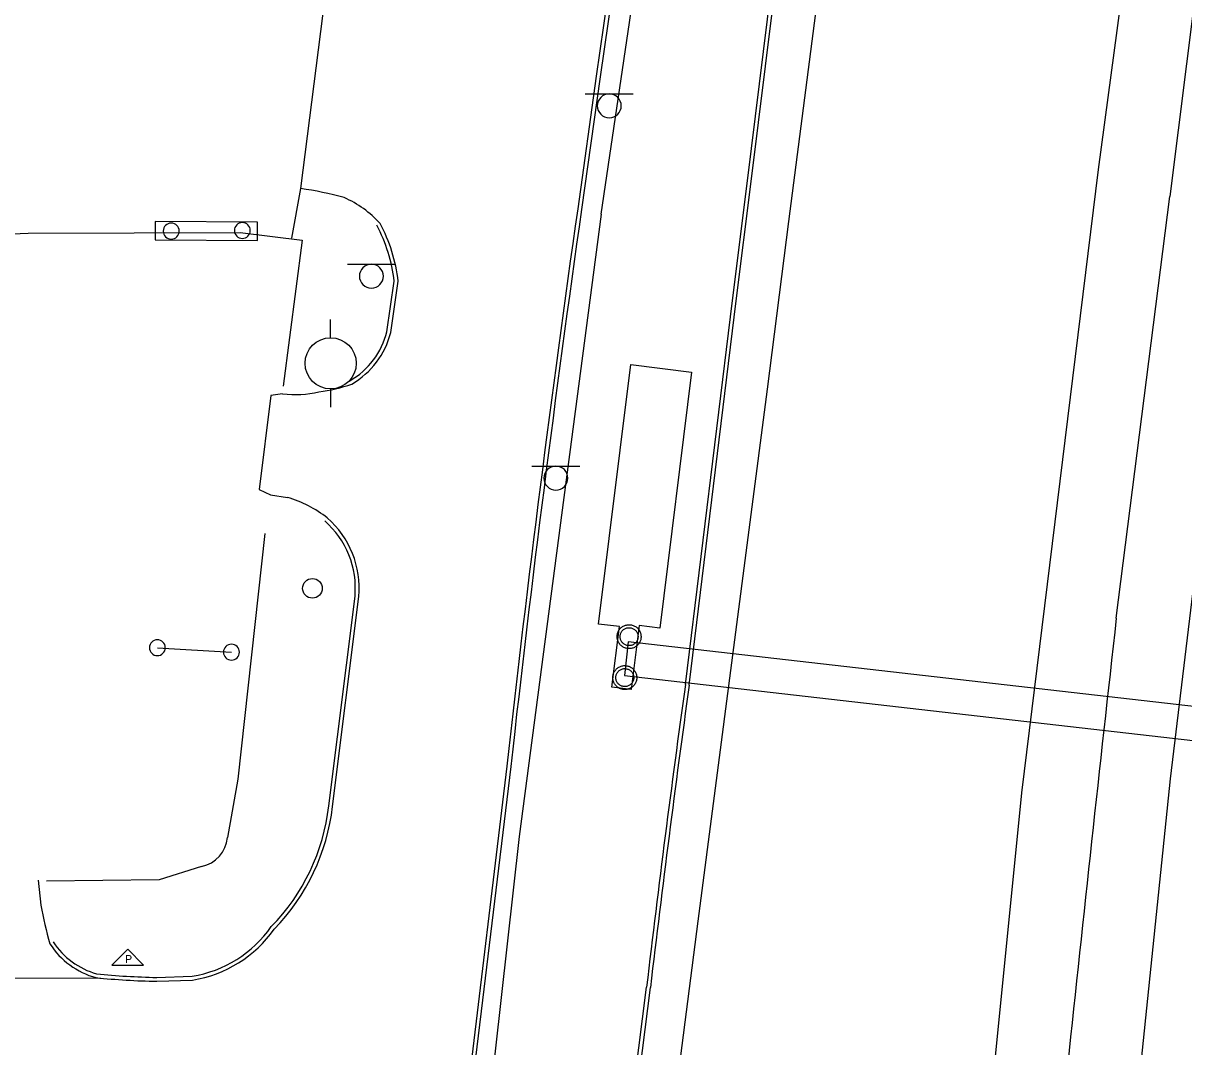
# Model space of a CAD drawing. Extents: x 2145380 to 2156929, y 139568 to 149130.
# Drawn here: x 2150672.3 to 2150853.5, y 146965.7 to 147125.6 of the extents above; entities that cross this region are included whole.
import ezdxf

# ---------------------------------------------------------------- set-up
doc = ezdxf.new("R2010")
doc.units = 0
for name, color, linetype in [('Default', 7, 'Continuous'), ('TOPO_Asphalt', 7, 'Continuous'), ('TOPO_Concrete', 7, 'Continuous'), ('TOPO_Curb Back', 7, 'Continuous'), ('TOPO_Fence', 7, 'Continuous'), ('TOPO_Guardrail', 7, 'Continuous'), ('TOPO_Misc', 7, 'Continuous'), ('TOPO_Power Pole', 7, 'Continuous'), ('TOPO_Sign', 7, 'Continuous'), ('TOPO_Wall Freestanding', 7, 'Continuous'), ('TOPO_Water Meter', 7, 'Continuous')]:
    doc.layers.add(name, color=color, linetype=linetype)

# ---------------------------------------------------------------- blocks, each defined once
blk = doc.blocks.new('POST')
at = {"layer": 'TOPO_Misc'}
for start, end in [(90, 180), (180, 270), (360, 90), (270, 0)]:
    blk.add_arc((-0.01, 0.03), 3.16, start, end, dxfattribs=at)
blk = doc.blocks.new('POWPOL')
at = {"layer": 'TOPO_Power Pole'}
for p, q in [((0, 10.16), (0, 17.34)), ((0, -10.16), (0, -17.34))]:
    blk.add_line(p, q, dxfattribs=at)
blk.add_circle((0, 0), 10.16, dxfattribs=at)
blk = doc.blocks.new('WTRMTR')
at = {"layer": 'Default'}
blk.add_circle((0, 0), 3.89, dxfattribs=at)

msp = doc.modelspace()

# ---------------------------------------------------------------- linework, layer by layer
at = {"layer": 'TOPO_Asphalt'}
for p, q in [((2150720.04, 147134.92), (2150715.57, 147099.73)), ((2150684.32, 146976.41), (2150650.56, 146976.32))]:
    msp.add_line(p, q, dxfattribs=at)
for points in [[(2151148.58, 148387.71), (2151085.35, 148183.97), (2151069.92, 148133.07), (2151057.83, 148094.37), (2151049.57, 148067.66), (2151035.93, 148022.98), (2151024.64, 147984.83), (2151012.64, 147943.42), (2151001.98, 147906), (2150990.9, 147865.2), (2150980.73, 147826.5), (2150968.97, 147781.23), (2150957.45, 147734.97), (2150948.5, 147698.21), (2150935.23, 147640.33), (2150928.26, 147609.37), (2150921.99, 147580.12), (2150903.41, 147490.92), (2150881.14, 147370.04), (2150865.32, 147276.63), (2150852.01, 147191.15), (2150840.13, 147102.7), (2150828.19, 147005.35), (2150817.7, 146900.58)], [(2150767.42, 146905.57), (2150777.66, 146985.28), (2150788.49, 147068.42), (2150791.81, 147094.61), (2150804.99, 147196.42), (2150817.4, 147289.05), (2150831.55, 147394.21), (2150843.61, 147487.04), (2150852.06, 147556.43)], [(2150819.78, 146571.32), (2150823.49, 146659.32), (2150828.97, 146758.61), (2150835.17, 146838.37), (2150842.86, 146924.28), (2150851.46, 147007.54), (2150862.87, 147102.56)], [(2150715.57, 147099.73), (2150714.18, 147092.01)], [(2150712.76, 147067.68), (2150710.93, 147067.41), (2150709.09, 147052.73), (2150710.88, 147051.89)], [(2150710.88, 147051.89), (2150713.55, 147051.5)], [(2150705.79, 147007.51), (2150704.16, 146998.38)], [(2150700.11, 146993.86), (2150693.5, 146991.77)], [(2150674.58, 146991.7), (2150675.01, 146987.81)]]:
    msp.add_lwpolyline(points, dxfattribs=at)
for centre, radius, start, end in [((2150708.73, 147049.63), 50.56, 74.3331, 82.2233), ((2150715.59, 147082.93), 16.82, 42.5079, 66.1666), ((2150715.52, 147091.91), 24.09, 276.9505, 289.5316), ((2150714.72, 147083.62), 16.06, 262.9859, 283.3625), ((2150707.95, 147033.11), 19.22, 52.1382, 73.0648), ((2150699.09, 146998.85), 5.1, 281.5826, 354.6962), ((2150736.07, 146998.83), 62.04, 190.2315, 195.9833)]:
    msp.add_arc(centre, radius, start, end, dxfattribs=at)
at = {"layer": 'TOPO_Concrete'}
msp.add_lwpolyline([(2150776.62, 147071.07), (2150771.68, 147031.09), (2150768.44, 147031.49), (2150767.21, 147021.51), (2150764.2, 147021.88), (2150765.37, 147031.32), (2150762.11, 147031.72), (2150767.13, 147072.25), (2150776.62, 147071.07)], dxfattribs=at)
at = {"layer": 'TOPO_Curb Back'}
for points in [[(2150846.01, 147581.74), (2150829.56, 147505.33), (2150818.69, 147452.43), (2150805.18, 147383.38), (2150793.7, 147320.64), (2150782.04, 147252.39), (2150770.34, 147176.72), (2150761.75, 147117.28), (2150758.85, 147096.56)], [(2150846.6, 147581.61), (2150830.15, 147505.21), (2150819.28, 147452.31), (2150805.77, 147383.26), (2150794.29, 147320.54), (2150782.63, 147252.3), (2150770.93, 147176.63), (2150762.35, 147117.2), (2150759.45, 147096.48)], [(2150775.68, 147022.26), (2150783.01, 147082.27), (2150785.37, 147100.94), (2150796.59, 147191.47), (2150808.98, 147283.55), (2150821.25, 147374.74), (2150832.7, 147461.73), (2150841, 147522.44), (2150851.09, 147556.17), (2150852.78, 147567.37)], [(2150776.27, 147022.18), (2150783.6, 147082.2), (2150785.97, 147100.86), (2150797.19, 147191.39), (2150809.57, 147283.47), (2150821.85, 147374.66), (2150833.3, 147461.65), (2150841.59, 147522.31), (2150851.68, 147556.04), (2150853.38, 147567.28)], [(2150729.07, 147077.38), (2150730.21, 147085.26)], [(2150729.66, 147077.26), (2150730.81, 147085.25)], [(2150719.97, 147003.3), (2150724.08, 147036.07)], [(2150720.57, 147003.23), (2150724.68, 147036)], [(2150747.79, 147009.54), (2150741.49, 146957.15), (2150734.18, 146889.26), (2150729.72, 146841.78), (2150726.33, 146801.59), (2150720.25, 146730.98), (2150714.67, 146662.78), (2150709.31, 146595.34), (2150703.43, 146516.5), (2150699.73, 146456.09), (2150696.04, 146382.8), (2150693.17, 146306.56), (2150691.24, 146222.87)], [(2150748.39, 147009.47), (2150742.08, 146957.08), (2150734.78, 146889.2), (2150730.32, 146841.72), (2150726.93, 146801.54), (2150720.84, 146730.93), (2150715.27, 146662.73), (2150709.91, 146595.3), (2150704.03, 146516.46), (2150700.33, 146456.06), (2150696.64, 146382.77), (2150693.77, 146306.54), (2150691.84, 146222.89)], [(2150693.09, 146976.52), (2150698.64, 146976.71)], [(2150693.1, 146975.92), (2150698.69, 146976.11)], [(2150716.37, 146556.85), (2150721.79, 146599.22), (2150730.66, 146669.12), (2150740.14, 146743.09), (2150749.46, 146815.03), (2150759.33, 146893.84), (2150769.62, 146975.01)], [(2150716.96, 146556.77), (2150722.39, 146599.15), (2150731.25, 146669.04), (2150740.73, 146743.01), (2150750.05, 146814.95), (2150759.92, 146893.77), (2150770.21, 146974.93)]]:
    msp.add_lwpolyline(points, dxfattribs=at)
for centre, radius, start, end in [((2153641.09, 146686.03), 2911.33, 171.89362, 173.62008), ((2153641.1, 146686.03), 2910.73, 171.89362, 173.62013), ((2150705.63, 147082.36), 24.75, 6.7241, 28.0992), ((2150705.63, 147082.36), 25.35, 6.5451, 28.099), ((2150717.13, 147080.39), 12.31, 299.9281, 345.8191), ((2150717.13, 147080.39), 12.91, 299.9276, 345.9591), ((2150710.21, 147037.32), 13.92, 354.8256, 48.9968), ((2150710.21, 147037.32), 14.52, 354.7849, 48.9964), ((2153014.01, 146711.08), 2259.86, 172.08526, 173.29311), ((2153014.94, 146710.95), 2260.2, 172.08526, 173.2928), ((2150687.84, 147007.04), 32.35, 315.713, 353.3641), ((2150687.84, 147007.04), 32.95, 315.798, 353.3595), ((2150695.71, 146995.13), 18.65, 279.0322, 325.063), ((2150695.71, 146995.13), 19.25, 278.9215, 324.9164), ((2150687.07, 146988.73), 12.73, 213.2757, 254.2011), ((2150687.07, 146988.73), 12.13, 213.2769, 253.9546), ((2150695.16, 147090.94), 115.04, 264.2353, 268.976), ((2150695.16, 147090.96), 114.46, 264.2626, 268.9679)]:
    msp.add_arc(centre, radius, start, end, dxfattribs=at)
at = {"layer": 'TOPO_Fence'}
for points in [[(2150762.5, 147095.73), (2150785.02, 147247.97), (2150805.17, 147364.3), (2150828.19, 147482.1)], [(2150762.52, 147095.73), (2150749.72, 146998.54), (2150739.48, 146906.78), (2150733.13, 146841.34), (2150726.96, 146767.54), (2150718.56, 146664.61), (2150710.62, 146567.84)]]:
    msp.add_lwpolyline(points, dxfattribs=at)
at = {"layer": 'TOPO_Guardrail'}
for p, q in [((2150710.01, 147045.86), (2150705.78, 147007.49)), ((2150693.5, 146991.77), (2150675.9, 146991.57))]:
    msp.add_line(p, q, dxfattribs=at)
msp.add_lwpolyline([(2150630.33, 147091.01), (2150673.02, 147092.77), (2150706.14, 147092.86), (2150715.82, 147091.66), (2150712.88, 147068.88)], dxfattribs=at)
at = {"layer": 'TOPO_Misc'}
for p, q in [((2150688.57, 146980.95), (2150686.07, 146978.45)), ((2150691.06, 146978.45), (2150688.57, 146980.95)), ((2150686.07, 146978.45), (2150691.06, 146978.45))]:
    msp.add_line(p, q, dxfattribs=at)
at = {"layer": 'TOPO_Power Pole'}
for points in [[(2150765.01, 147029.74), (2150765.01, 147029.87), (2150765.03, 147030), (2150765.05, 147030.13), (2150765.09, 147030.26), (2150765.13, 147030.38), (2150765.18, 147030.51), (2150765.24, 147030.63), (2150765.3, 147030.74), (2150765.38, 147030.85), (2150765.46, 147030.96), (2150765.55, 147031.05), (2150765.64, 147031.15), (2150765.75, 147031.23), (2150765.86, 147031.31), (2150765.97, 147031.37), (2150766.09, 147031.43), (2150766.21, 147031.48), (2150766.33, 147031.53), (2150766.46, 147031.56), (2150766.6, 147031.59), (2150766.73, 147031.61), (2150766.86, 147031.61), (2150766.99, 147031.61), (2150767.12, 147031.59), (2150767.25, 147031.58), (2150767.37, 147031.54), (2150767.5, 147031.51), (2150767.62, 147031.45), (2150767.75, 147031.4), (2150767.86, 147031.34), (2150767.97, 147031.26), (2150768.08, 147031.18), (2150768.17, 147031.1), (2150768.27, 147031), (2150768.35, 147030.9), (2150768.43, 147030.79), (2150768.5, 147030.68), (2150768.57, 147030.56), (2150768.62, 147030.44), (2150768.66, 147030.31), (2150768.7, 147030.19), (2150768.73, 147030.06), (2150768.74, 147029.92), (2150768.75, 147029.79), (2150768.75, 147029.67), (2150768.74, 147029.53), (2150768.72, 147029.4), (2150768.69, 147029.27), (2150768.65, 147029.15), (2150768.61, 147029.02), (2150768.55, 147028.91), (2150768.49, 147028.79), (2150768.42, 147028.68), (2150768.34, 147028.57), (2150768.25, 147028.46), (2150768.16, 147028.37), (2150768.06, 147028.29), (2150767.95, 147028.21), (2150767.84, 147028.14), (2150767.73, 147028.07), (2150767.61, 147028.02), (2150767.48, 147027.97), (2150767.35, 147027.93), (2150767.23, 147027.9), (2150767.09, 147027.88), (2150766.96, 147027.87), (2150766.84, 147027.87), (2150766.71, 147027.88), (2150766.58, 147027.89), (2150766.44, 147027.92), (2150766.32, 147027.96), (2150766.19, 147028.01), (2150766.07, 147028.06), (2150765.95, 147028.12), (2150765.84, 147028.19), (2150765.73, 147028.27), (2150765.63, 147028.35), (2150765.54, 147028.44), (2150765.45, 147028.54), (2150765.37, 147028.65), (2150765.29, 147028.76), (2150765.23, 147028.87), (2150765.17, 147028.99), (2150765.12, 147029.12), (2150765.08, 147029.24), (2150765.05, 147029.36), (2150765.03, 147029.5), (2150765.01, 147029.63), (2150765.01, 147029.74)], [(2150765.48, 147029.74), (2150765.48, 147029.85), (2150765.5, 147029.97), (2150765.52, 147030.08), (2150765.56, 147030.19), (2150765.59, 147030.3), (2150765.64, 147030.4), (2150765.7, 147030.49), (2150765.77, 147030.59), (2150765.84, 147030.68), (2150765.92, 147030.76), (2150766.01, 147030.84), (2150766.11, 147030.91), (2150766.2, 147030.96), (2150766.3, 147031.01), (2150766.41, 147031.06), (2150766.52, 147031.1), (2150766.63, 147031.12), (2150766.74, 147031.14), (2150766.86, 147031.14), (2150766.97, 147031.14), (2150767.08, 147031.13), (2150767.2, 147031.11), (2150767.31, 147031.07), (2150767.41, 147031.04), (2150767.52, 147030.99), (2150767.61, 147030.93), (2150767.71, 147030.87), (2150767.8, 147030.8), (2150767.89, 147030.72), (2150767.96, 147030.63), (2150768.03, 147030.54), (2150768.09, 147030.44), (2150768.15, 147030.34), (2150768.19, 147030.24), (2150768.23, 147030.13), (2150768.26, 147030.02), (2150768.27, 147029.9), (2150768.28, 147029.79), (2150768.28, 147029.68), (2150768.27, 147029.57), (2150768.25, 147029.46), (2150768.23, 147029.34), (2150768.19, 147029.23), (2150768.14, 147029.13), (2150768.09, 147029.03), (2150768.03, 147028.93), (2150767.96, 147028.84), (2150767.88, 147028.76), (2150767.8, 147028.68), (2150767.7, 147028.61), (2150767.61, 147028.55), (2150767.51, 147028.49), (2150767.4, 147028.44), (2150767.3, 147028.4), (2150767.18, 147028.37), (2150767.07, 147028.35), (2150766.95, 147028.34), (2150766.85, 147028.34), (2150766.74, 147028.35), (2150766.63, 147028.36), (2150766.51, 147028.38), (2150766.4, 147028.42), (2150766.3, 147028.46), (2150766.19, 147028.52), (2150766.1, 147028.58), (2150766, 147028.65), (2150765.92, 147028.72), (2150765.84, 147028.81), (2150765.76, 147028.9), (2150765.69, 147028.99), (2150765.64, 147029.09), (2150765.59, 147029.19), (2150765.55, 147029.3), (2150765.52, 147029.41), (2150765.5, 147029.52), (2150765.48, 147029.64), (2150765.48, 147029.74)], [(2150764.33, 147023.35), (2150764.34, 147023.48), (2150764.35, 147023.61), (2150764.38, 147023.73), (2150764.41, 147023.87), (2150764.45, 147023.99), (2150764.5, 147024.12), (2150764.56, 147024.23), (2150764.63, 147024.35), (2150764.71, 147024.46), (2150764.79, 147024.56), (2150764.87, 147024.66), (2150764.97, 147024.75), (2150765.07, 147024.83), (2150765.18, 147024.92), (2150765.3, 147024.98), (2150765.42, 147025.04), (2150765.53, 147025.09), (2150765.66, 147025.13), (2150765.79, 147025.17), (2150765.92, 147025.19), (2150766.05, 147025.22), (2150766.19, 147025.22), (2150766.31, 147025.22), (2150766.44, 147025.2), (2150766.57, 147025.18), (2150766.7, 147025.15), (2150766.83, 147025.11), (2150766.95, 147025.06), (2150767.07, 147025.01), (2150767.19, 147024.94), (2150767.3, 147024.87), (2150767.4, 147024.79), (2150767.5, 147024.7), (2150767.59, 147024.61), (2150767.68, 147024.5), (2150767.75, 147024.39), (2150767.83, 147024.28), (2150767.89, 147024.17), (2150767.94, 147024.04), (2150767.99, 147023.92), (2150768.02, 147023.79), (2150768.05, 147023.66), (2150768.07, 147023.53), (2150768.08, 147023.4), (2150768.08, 147023.28), (2150768.07, 147023.14), (2150768.05, 147023.01), (2150768.02, 147022.88), (2150767.98, 147022.75), (2150767.94, 147022.63), (2150767.88, 147022.51), (2150767.82, 147022.39), (2150767.75, 147022.28), (2150767.66, 147022.18), (2150767.58, 147022.07), (2150767.48, 147021.98), (2150767.39, 147021.9), (2150767.28, 147021.82), (2150767.17, 147021.74), (2150767.05, 147021.68), (2150766.93, 147021.63), (2150766.81, 147021.58), (2150766.68, 147021.54), (2150766.55, 147021.51), (2150766.42, 147021.49), (2150766.29, 147021.48), (2150766.16, 147021.48), (2150766.03, 147021.49), (2150765.9, 147021.5), (2150765.77, 147021.53), (2150765.65, 147021.57), (2150765.52, 147021.61), (2150765.4, 147021.66), (2150765.28, 147021.73), (2150765.17, 147021.79), (2150765.06, 147021.88), (2150764.95, 147021.96), (2150764.86, 147022.05), (2150764.77, 147022.15), (2150764.69, 147022.26), (2150764.62, 147022.37), (2150764.55, 147022.48), (2150764.5, 147022.6), (2150764.44, 147022.73), (2150764.4, 147022.85), (2150764.38, 147022.97), (2150764.35, 147023.11), (2150764.34, 147023.24), (2150764.33, 147023.35)], [(2150764.8, 147023.35), (2150764.81, 147023.46), (2150764.82, 147023.58), (2150764.85, 147023.68), (2150764.88, 147023.79), (2150764.92, 147023.9), (2150764.97, 147024.01), (2150765.03, 147024.1), (2150765.1, 147024.2), (2150765.17, 147024.28), (2150765.25, 147024.37), (2150765.34, 147024.45), (2150765.43, 147024.51), (2150765.53, 147024.57), (2150765.63, 147024.62), (2150765.73, 147024.67), (2150765.84, 147024.7), (2150765.96, 147024.73), (2150766.07, 147024.75), (2150766.19, 147024.75), (2150766.3, 147024.75), (2150766.4, 147024.74), (2150766.52, 147024.72), (2150766.63, 147024.68), (2150766.74, 147024.64), (2150766.85, 147024.6), (2150766.94, 147024.54), (2150767.04, 147024.48), (2150767.13, 147024.4), (2150767.21, 147024.33), (2150767.29, 147024.24), (2150767.36, 147024.14), (2150767.42, 147024.05), (2150767.47, 147023.95), (2150767.52, 147023.84), (2150767.55, 147023.73), (2150767.59, 147023.63), (2150767.6, 147023.51), (2150767.61, 147023.4), (2150767.61, 147023.29), (2150767.6, 147023.18), (2150767.58, 147023.06), (2150767.55, 147022.95), (2150767.51, 147022.84), (2150767.47, 147022.74), (2150767.42, 147022.64), (2150767.35, 147022.54), (2150767.29, 147022.45), (2150767.2, 147022.37), (2150767.12, 147022.28), (2150767.03, 147022.21), (2150766.93, 147022.15), (2150766.84, 147022.09), (2150766.73, 147022.04), (2150766.63, 147022.01), (2150766.51, 147021.98), (2150766.4, 147021.96), (2150766.28, 147021.95), (2150766.18, 147021.95), (2150766.06, 147021.96), (2150765.95, 147021.97), (2150765.83, 147021.99), (2150765.72, 147022.03), (2150765.62, 147022.07), (2150765.52, 147022.13), (2150765.42, 147022.19), (2150765.33, 147022.26), (2150765.24, 147022.33), (2150765.16, 147022.42), (2150765.09, 147022.5), (2150765.02, 147022.6), (2150764.97, 147022.69), (2150764.92, 147022.8), (2150764.87, 147022.91), (2150764.85, 147023.02), (2150764.82, 147023.13), (2150764.81, 147023.24), (2150764.8, 147023.35)]]:
    msp.add_lwpolyline(points, dxfattribs=at)
at = {"layer": 'TOPO_Sign'}
for points in [[(2150760.04, 147114.53), (2150767.53, 147114.53)], [(2150763.79, 147114.52), (2150763.79, 147114.52)], [(2150761.92, 147112.66), (2150761.92, 147112.66)], [(2150765.66, 147112.66), (2150765.66, 147112.66)], [(2150763.79, 147110.79), (2150763.79, 147110.79)], [(2150722.88, 147087.92), (2150730.37, 147087.93)], [(2150726.63, 147087.92), (2150726.63, 147087.92)], [(2150724.76, 147086.05), (2150724.76, 147086.05)], [(2150728.49, 147086.05), (2150728.49, 147086.05)], [(2150726.63, 147084.18), (2150726.63, 147084.18)], [(2150751.7, 147056.38), (2150759.2, 147056.39)], [(2150755.45, 147056.38), (2150755.45, 147056.38)], [(2150753.58, 147054.51), (2150753.58, 147054.51)], [(2150757.32, 147054.51), (2150757.32, 147054.51)], [(2150755.45, 147052.65), (2150755.45, 147052.65)], [(2150693.21, 147028.01), (2150704.78, 147027.31)]]:
    msp.add_lwpolyline(points, dxfattribs=at)
for points in [[(2150708.85, 147094.46), (2150692.87, 147094.61), (2150692.85, 147091.75), (2150708.82, 147091.6)], [(2150766.15, 147023.69), (2150915.92, 147006.57), (2150916.51, 147011.78), (2150766.74, 147028.91)]]:
    msp.add_lwpolyline(points, close=True, dxfattribs=at)
for centre, start, end in [((2150763.79, 147112.66), 90, 180), ((2150763.79, 147112.66), 360, 90), ((2150763.79, 147112.66), 180, 270), ((2150763.79, 147112.66), 270, 0), ((2150726.63, 147086.05), 90, 180), ((2150726.63, 147086.05), 360, 90), ((2150726.63, 147086.05), 180, 270), ((2150726.63, 147086.05), 270, 0), ((2150755.45, 147054.51), 90, 180), ((2150755.45, 147054.51), 360, 90), ((2150755.45, 147054.51), 180, 270), ((2150755.45, 147054.51), 270, 0)]:
    msp.add_arc(centre, 1.87, start, end, dxfattribs=at)
at = {"layer": 'TOPO_Wall Freestanding'}
for points in [[(2151336.32, 148953.74), (2151322.23, 148907.93), (2151284.28, 148786.3), (2151239.81, 148641.85), (2151199.12, 148510.75), (2151182.1, 148455.86), (2151142.3, 148328), (2151095.05, 148175.91), (2151053.71, 148043.16), (2150993.17, 147829.95), (2150947.4, 147643.21), (2150938.13, 147601.94), (2150921.17, 147523), (2150897.57, 147399.22), (2150877.65, 147284.38), (2150857.8, 147149.76), (2150851.31, 147098.47)], [(2150842.97, 147032.61), (2150851.31, 147098.47)]]:
    msp.add_lwpolyline(points, dxfattribs=at)
msp.add_arc((2160906.81, 145901.62), 10127.19, 173.587887, 174.381354, dxfattribs=at)

# ---------------------------------------------------------------- block references
at = {"layer": 'TOPO_Misc', "xscale": 0.39370000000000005, "yscale": 0.3937000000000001}
for p in [(2150695.38, 147093.08), (2150706.48, 147093.17), (2150693.21, 147028.01), (2150704.78, 147027.31)]:
    msp.add_blockref('POST', p, dxfattribs=at)
at = {"layer": 'TOPO_Power Pole', "xscale": 0.39370000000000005, "yscale": 0.3937000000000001}
msp.add_blockref('POWPOL', (2150720.27, 147072.44), dxfattribs=at)
at = {"layer": 'TOPO_Water Meter', "xscale": 0.39370000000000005, "yscale": 0.3937000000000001}
msp.add_blockref('WTRMTR', (2150717.43, 147037.29), dxfattribs=at)

# ---------------------------------------------------------------- texts
at = {"layer": 'TOPO_Misc'}
msp.add_text('P', height=1.25, dxfattribs=at).set_placement((2150688.15, 146978.76))

doc.saveas('drawing.dxf')
